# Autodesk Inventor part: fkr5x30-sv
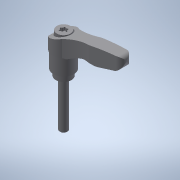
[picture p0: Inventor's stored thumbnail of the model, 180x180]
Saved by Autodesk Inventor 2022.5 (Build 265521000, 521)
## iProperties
Created: 2016-12
Part Number: fkr5x30-sv
Material: 一般
Document SubType Name: Modeling
Designer: imaocorp
Density: 1 g/cm^3
Appearance: 既定
Author: imaocorp
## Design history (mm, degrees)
node "fkr5x30-sv.x_t1"
node "K1000_105010_011"
node "Base1"
